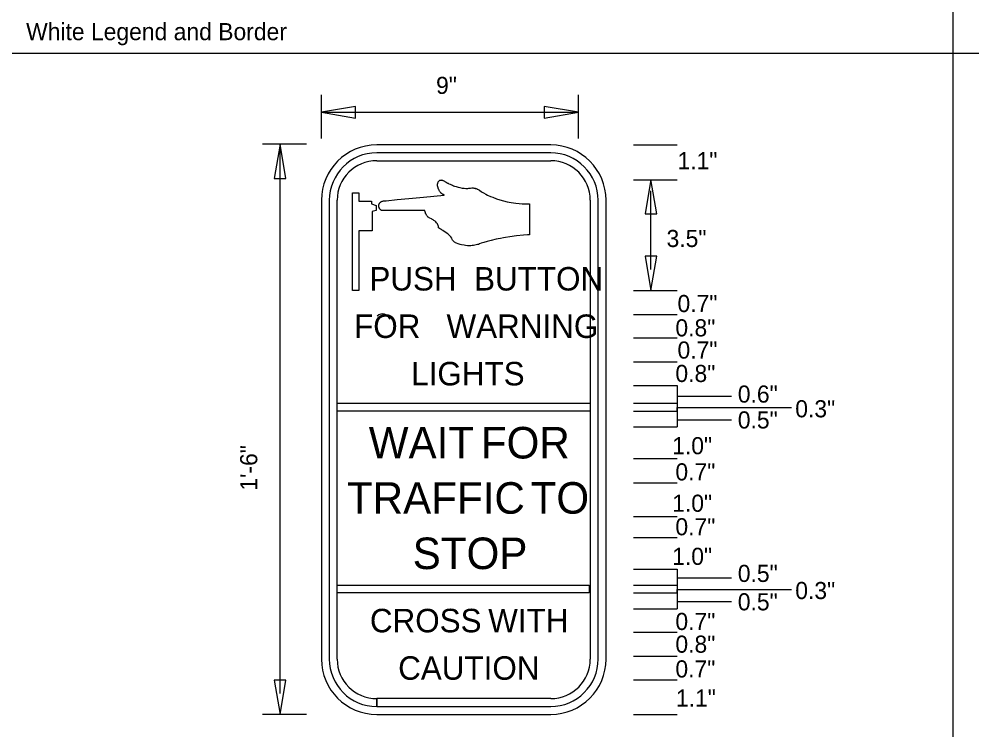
# Model space of a CAD drawing. Extents: x 0 to 770, y 0 to 495.
# Drawn here: x 386.5 to 581.3, y 191.6 to 337 of the extents above; entities that cross this region are included whole.
import ezdxf

# ---------------------------------------------------------------- set-up
doc = ezdxf.new("R2010")
doc.units = 0
for name, color, linetype in [('Default', 7, 'Continuous'), ('Dimension', 7, 'Continuous'), ('GSBWFill', 7, 'Continuous'), ('GSDims', 7, 'Continuous'), ('SheetLines_dp', 7, 'Continuous'), ('SignPanel', 7, 'Continuous'), ('TextStructures', 7, 'Continuous')]:
    doc.layers.add(name, color=color, linetype=linetype)

msp = doc.modelspace()

# ---------------------------------------------------------------- linework, layer by layer
at = {"layer": 'Default'}
for p, q in [((521.06, 262.1), (521.06, 258.45)), ((521.06, 259.92), (532.18, 259.92)), ((521.06, 256.83), (521.06, 253.6)), ((521.06, 255.07), (532.18, 255.07)), ((521.06, 224.54), (521.06, 221.28)), ((521.06, 222.75), (532.18, 222.75)), ((521.06, 219.66), (521.06, 216.41)), ((521.06, 217.88), (532.18, 217.88))]:
    msp.add_line(p, q, dxfattribs=at)
for points in [[(490.87, 299.25), (490.87, 292.89), (490.47, 292.86), (489.6, 292.79), (488.19, 292.65), (486.85, 292.48), (485.91, 292.34), (485.56, 292.28), (484.94, 292.17), (484.43, 292.07), (484.06, 292), (483.03, 291.76), (482.18, 291.53), (481.53, 291.33), (480.98, 291.15), (480.64, 291.03), (480.39, 290.93), (480.21, 290.88), (479.94, 290.82), (479.43, 290.73), (479.15, 290.69), (478.86, 290.65), (478.66, 290.64), (478.19, 290.65), (478.19, 290.65), (477.75, 290.72), (477.47, 290.77), (476.92, 290.87), (476.64, 290.94), (476.23, 291.06), (475.9, 291.19), (475.75, 291.26), (475.62, 291.34), (475.48, 291.42), (475.31, 291.57), (475.31, 291.57), (475.11, 291.78), (475.05, 291.96), (474.96, 292.18), (474.74, 292.51), (474.56, 292.7), (474.16, 293.06), (473.59, 293.46), (473.15, 293.76), (472.99, 293.87), (472.83, 293.96), (472.64, 294.07), (472.46, 294.18), (472.38, 294.23), (472.32, 294.28), (472.28, 294.32), (472.27, 294.35), (472.26, 294.37), (472.25, 294.42), (472.23, 294.53), (472.21, 294.64), (472.18, 294.76), (472.16, 294.82), (472.13, 294.9), (472.1, 294.98), (472.06, 295.05), (472.01, 295.14), (471.97, 295.2), (471.92, 295.27), (471.86, 295.34), (471.7, 295.53), (471.56, 295.65), (471.43, 295.75), (471.3, 295.84), (471.12, 295.96), (471, 296.04), (470.85, 296.11), (470.78, 296.15), (470.47, 296.31), (470.35, 296.38), (470.23, 296.45), (470.11, 296.51), (470.08, 296.53), (470.03, 296.58), (469.95, 296.69), (469.85, 296.84), (469.78, 296.93), (469.69, 297.1), (469.61, 297.27), (469.58, 297.36), (469.55, 297.43), (469.52, 297.54), (469.49, 297.64), (469.47, 297.76), (469.46, 297.84), (469.24, 297.84), (467.38, 297.84), (463.71, 297.84), (461.38, 297.85), (460.92, 297.85), (460.84, 297.85), (460.76, 297.85), (460.74, 297.85), (460.72, 297.85), (460.69, 297.86), (460.65, 297.87), (460.63, 297.87), (460.59, 297.88), (460.54, 297.9), (460.52, 297.92), (460.43, 297.97), (460.37, 298.02), (460.31, 298.08), (460.27, 298.12), (460.24, 298.16), (460.15, 298.32), (460.12, 298.36), (460.08, 298.47), (460.05, 298.57), (460.02, 298.7), (460.02, 298.76), (460.02, 298.84), (460.02, 298.9), (460.03, 298.99), (460.06, 299.09), (460.09, 299.17), (460.12, 299.24), (460.17, 299.34), (460.21, 299.39), (460.25, 299.44), (460.28, 299.47), (460.32, 299.51), (460.42, 299.58), (460.47, 299.61), (460.57, 299.67), (460.64, 299.7), (460.73, 299.74), (460.83, 299.77), (460.87, 299.78), (460.99, 299.81), (461.06, 299.82), (461.51, 299.86), (463.79, 300.08), (466.2, 300.32), (469.17, 300.6), (473.41, 301.01), (473.42, 301.01), (473.42, 301.03), (473.38, 301.05), (473.35, 301.06), (473.29, 301.09), (473.24, 301.11), (473.19, 301.13), (473.13, 301.16), (473.09, 301.18), (473.04, 301.22), (473, 301.24), (472.93, 301.29), (472.9, 301.31), (472.83, 301.36), (472.78, 301.41), (472.75, 301.43), (472.73, 301.45), (472.69, 301.49), (472.64, 301.56), (472.58, 301.63), (472.51, 301.74), (472.45, 301.82), (472.39, 301.92), (472.35, 302), (472.3, 302.06), (472.28, 302.13), (472.25, 302.25), (472.19, 302.41), (472.16, 302.5), (472.14, 302.58), (472.12, 302.63), (472.11, 302.68), (472.09, 302.78), (472.07, 302.86), (472.07, 302.93), (472.06, 303), (472.06, 303.05), (472.06, 303.15), (472.07, 303.24), (472.07, 303.31), (472.08, 303.36), (472.1, 303.45), (472.11, 303.48), (472.13, 303.54), (472.16, 303.64), (472.19, 303.71), (472.22, 303.78), (472.28, 303.87), (472.35, 303.96), (472.42, 304.01), (472.48, 304.04), (472.48, 304.04), (472.54, 304.06), (472.58, 304.08), (472.64, 304.08), (472.75, 304.09), (472.84, 304.09), (472.92, 304.1), (472.95, 304.09), (473.04, 304.05), (473.12, 304.02), (473.19, 303.99), (473.31, 303.92), (473.46, 303.84), (473.52, 303.8), (473.64, 303.73), (473.79, 303.63), (474, 303.52), (474.08, 303.48), (474.19, 303.43), (474.38, 303.34), (474.6, 303.24), (474.74, 303.18), (474.87, 303.12), (475.08, 303.03), (475.3, 302.94), (475.53, 302.85), (475.84, 302.75), (476.23, 302.63), (476.59, 302.54), (477.07, 302.45), (477.5, 302.4), (477.84, 302.37), (478.09, 302.36), (478.25, 302.38), (478.46, 302.4), (478.78, 302.46), (479.05, 302.5), (479.17, 302.51), (479.29, 302.51), (479.36, 302.5), (479.49, 302.46), (479.71, 302.4), (479.93, 302.32), (480.01, 302.33), (480.25, 302.24), (480.65, 301.99), (481.05, 301.71), (481.43, 301.47), (481.89, 301.23), (482.27, 301.03), (482.9, 300.74), (483.34, 300.56), (484.12, 300.26), (484.78, 300.05), (485.53, 299.83), (486.29, 299.65), (487.1, 299.49), (488.04, 299.35), (488.71, 299.28), (489.33, 299.25), (489.99, 299.23), (490.45, 299.22), (490.69, 299.22), (490.84, 299.21)], [(454.67, 301.47), (455.92, 301.47), (455.92, 299.78), (458.56, 299.78), (458.56, 299.24), (459.51, 298.86), (459.52, 297.84), (458.66, 297.64), (458.67, 293.72), (455.92, 293.72), (455.92, 281.48), (454.67, 281.48)], [(451.52, 258.45), (503.28, 258.45), (503.28, 256.83), (451.52, 256.83)], [(451.52, 221.28), (503.05, 221.28), (503.05, 219.66), (451.52, 219.66)]]:
    msp.add_lwpolyline(points, close=True, dxfattribs=at)
for points in [[(521.06, 258.45), (521.06, 256.83), (521.06, 257.56), (544.43, 257.56)], [(521.06, 221.28), (521.06, 219.66), (521.06, 220.39), (544.43, 220.39)]]:
    msp.add_lwpolyline(points, dxfattribs=at)
msp.add_arc((460.8, 275.12), 1.58, 15.7828, 132.9396, dxfattribs=at)
at = {"layer": 'Dimension'}
for points in [[(448.29, 317.95), (455.3, 316.76), (455.3, 319.14)], [(500.87, 317.95), (493.85, 319.14), (493.85, 316.76)], [(439.85, 311.4), (438.66, 304.38), (441.04, 304.38)], [(515.69, 304.17), (514.5, 297.16), (516.88, 297.16)], [(515.69, 281.5), (516.88, 288.51), (514.5, 288.51)], [(439.85, 194.82), (441.04, 201.84), (438.66, 201.84)]]:
    msp.add_lwpolyline(points, close=True, dxfattribs=at)
at = {"layer": 'GSBWFill'}
for p, q in [((495.19, 311.27), (459.61, 311.27)), ((495.19, 309.65), (459.61, 309.65)), ((459.61, 308.04), (495.19, 308.04)), ((448.29, 299.95), (448.29, 206.14)), ((449.9, 299.95), (449.9, 206.14)), ((451.52, 206.14), (451.52, 299.95)), ((503.28, 299.95), (503.28, 206.14)), ((504.89, 206.14), (504.89, 299.95)), ((506.51, 206.14), (506.51, 299.95)), ((459.61, 196.44), (459.61, 198.05)), ((495.19, 198.05), (459.62, 198.05)), ((459.62, 198.05), (459.62, 196.44)), ((459.62, 196.44), (495.19, 196.44)), ((459.61, 194.82), (495.19, 194.82))]:
    msp.add_line(p, q, dxfattribs=at)
for centre, radius, start, end in [((459.61, 299.95), 11.32, 90, 180), ((495.19, 299.95), 11.32, 0, 90), ((459.61, 299.95), 9.7, 90, 180), ((459.61, 299.95), 8.09, 90, 180), ((495.19, 299.95), 9.7, 0, 90), ((495.19, 299.95), 8.09, 0, 90), ((459.61, 206.14), 11.32, 180, 270), ((459.61, 206.14), 9.7, 180, 270), ((459.61, 206.14), 8.09, 180, 270), ((495.19, 206.14), 9.7, 270, 0), ((495.19, 206.14), 8.09, 270, 0), ((495.19, 206.14), 11.32, 270, 0)]:
    msp.add_arc(centre, radius, start, end, dxfattribs=at)
at = {"layer": 'GSDims'}
for p, q in [((448.29, 312.57), (448.29, 321.53)), ((500.87, 312.57), (500.87, 321.53)), ((448.29, 317.95), (500.87, 317.95)), ((445.22, 311.4), (436.27, 311.4)), ((439.85, 199.11), (439.85, 311.4)), ((512.11, 311.27), (521.06, 311.27)), ((512.11, 304.1), (521.06, 304.1)), ((515.69, 285.78), (515.69, 301.91)), ((512.11, 281.5), (521.06, 281.5)), ((512.11, 281.5), (521.06, 281.5)), ((512.11, 276.6), (521.06, 276.6)), ((512.11, 271.8), (521.06, 271.8)), ((512.11, 266.9), (521.06, 266.9)), ((512.11, 262.1), (521.06, 262.1)), ((512.11, 258.45), (521.06, 258.45)), ((512.11, 256.83), (521.06, 256.83)), ((512.11, 253.6), (521.06, 253.6)), ((512.11, 247.16), (521.06, 247.16)), ((512.11, 242.2), (521.06, 242.2)), ((512.11, 235.29), (521.06, 235.29)), ((512.11, 230.98), (521.06, 230.98)), ((512.11, 224.54), (521.06, 224.54)), ((512.11, 221.28), (521.06, 221.28)), ((512.11, 219.66), (521.06, 219.66)), ((512.11, 216.41), (521.06, 216.41)), ((512.11, 211.61), (521.06, 211.61)), ((512.11, 206.71), (521.06, 206.71)), ((512.11, 201.91), (521.06, 201.91)), ((445.22, 194.82), (436.27, 194.82)), ((512.11, 194.82), (521.06, 194.82))]:
    msp.add_line(p, q, dxfattribs=at)
at = {"layer": 'SheetLines_dp'}
for p, q in [((577.5, 0), (577.5, 495)), ((0, 330), (770, 330))]:
    msp.add_line(p, q, dxfattribs=at)

# ---------------------------------------------------------------- texts
at = {"layer": 'SignPanel'}
for s, height, p in [('PUSH  BUTTON', 4.802, (458.11, 281.5)), ('FOR   WARNING', 4.802, (454.98, 271.8)), ('LIGHTS', 4.802, (466.66, 262.1)), ('WAIT', 6.446, (457.98, 247.16)), ('FOR', 6.446, (480.9, 247.16)), ('TRAFFIC', 6.446, (453.51, 235.86)), ('TO', 6.446, (491.08, 235.87)), ('STOP', 6.446, (466.96, 224.54)), ('CROSS', 4.802, (458.21, 211.61)), ('WITH', 4.802, (482.41, 211.61)), ('CAUTION', 4.802, (463.99, 201.91))]:
    msp.add_text(s, height=height, dxfattribs=at).set_placement(p)
at = {"layer": 'TextStructures'}
for s, p in [('White Legend and Border', (387.9, 332.69)), ('9"', (471.74, 321.7)), ('1.1"', (521.12, 306.3)), ('3.5"', (518.88, 290.39)), ('0.7"', (521.12, 277.09)), ('0.8"', (520.69, 272.12)), ('0.7"', (521.12, 267.58)), ('0.8"', (520.69, 262.79)), ('0.6"', (533.45, 258.58)), ('0.3"', (545.2, 255.57)), ('0.5"', (533.45, 253.29)), ('1.0"', (520.03, 248.02)), ('0.7"', (520.69, 242.67)), ('1.0"', (520.03, 236.26)), ('0.7"', (520.69, 231.45)), ('1.0"', (520.03, 225.4)), ('0.5"', (533.45, 221.91)), ('0.3"', (545.2, 218.41)), ('0.5"', (533.45, 216.1)), ('0.7"', (520.69, 212.08)), ('0.8"', (520.69, 207.44)), ('0.7"', (520.69, 202.38)), ('1.1"', (520.79, 196.42))]:
    msp.add_text(s, height=3.5, dxfattribs=at).set_placement(p)
msp.add_text('1\'-6"', height=3.5, rotation=90, dxfattribs=at).set_placement((435.18, 240.57))

doc.saveas('drawing.dxf')
